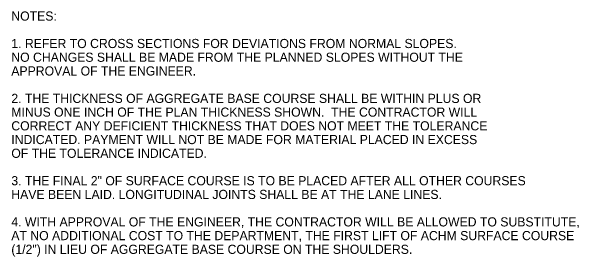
# Model space of a CAD drawing. Extents: x -900 to 15312, y 1857 to 2945.
# Drawn here: x 4626.2 to 4998.6, y 2484.6 to 2645.5 of the extents above; entities that cross this region are included whole.
import ezdxf

# ---------------------------------------------------------------- set-up
doc = ezdxf.new("R2010")
doc.units = 0
doc.layers.add('R_Annotation', color=7, linetype='Continuous')

msp = doc.modelspace()

# ---------------------------------------------------------------- texts
at = {"layer": 'R_Annotation'}
for s, p in [('NOTES:', (4626.22, 2639.37)), ('1. REFER TO CROSS SECTIONS FOR DEVIATIONS FROM NORMAL SLOPES. ', (4626.22, 2621.37)), ('NO CHANGES SHALL BE MADE FROM THE PLANNED SLOPES WITHOUT THE', (4626.22, 2612.37)), ('APPROVAL OF THE ENGINEER.', (4626.22, 2603.37)), ('2. THE THICKNESS OF AGGREGATE BASE COURSE SHALL BE WITHIN PLUS OR', (4626.22, 2585.37)), ('MINUS ONE INCH OF THE PLAN THICKNESS SHOWN.  THE CONTRACTOR WILL', (4626.22, 2576.37)), ('CORRECT ANY DEFICIENT THICKNESS THAT DOES NOT MEET THE TOLERANCE', (4626.22, 2567.37)), ('INDICATED. PAYMENT WILL NOT BE MADE FOR MATERIAL PLACED IN EXCESS', (4626.22, 2558.37)), ('OF THE TOLERANCE INDICATED.', (4626.22, 2549.37)), ('3. THE FINAL 2" OF SURFACE COURSE IS TO BE PLACED AFTER ALL OTHER COURSES', (4626.22, 2531.37)), ('HAVE BEEN LAID. LONGITUDINAL JOINTS SHALL BE AT THE LANE LINES.', (4626.22, 2522.37)), ('4. WITH APPROVAL OF THE ENGINEER, THE CONTRACTOR WILL BE ALLOWED TO SUBSTITUTE,', (4626.22, 2504.37)), ('AT NO ADDITIONAL COST TO THE DEPARTMENT, THE FIRST LIFT OF ACHM SURFACE COURSE', (4626.22, 2495.37)), ('(1/2") IN LIEU OF AGGREGATE BASE COURSE ON THE SHOULDERS.', (4626.22, 2486.37))]:
    msp.add_text(s, height=6, dxfattribs=at).set_placement(p)

doc.saveas('drawing.dxf')
